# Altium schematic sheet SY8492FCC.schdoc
size 127 x 101 mm
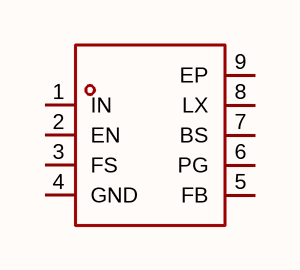
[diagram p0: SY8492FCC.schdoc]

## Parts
U?  sy8492fcc  [SO-8_L4.9-W3.9-P1.27-LS6.0-BL-EP]  (value not drawn)

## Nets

Not connected (* = marked no-connect by the designer): U? 1(IN) 2(EN) 3(FS) 4(GND) 5(FB) 6(PG) 7(BS) 8(LX) 9(EP)

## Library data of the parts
U? = sy8492fcc: 功能类型:降压型;工作电压:4.5V~60V;输出电压:800mV~60V;输出电流:2A;输出类型:可调;; Manufacturer: Silergy(矽力杰); AddInBom: yes; ModelId: 756fba4e187a48c69a2c935cd5c4465b; ModelName: SO-8_L4.9-W3.9-H1.5-LS5.9-P1.27; ModelTransform: 240.39054,192.913,0,270,0,0,0.004,-0.002,0; Function: 降压型; Output Current: 2A; Frequency - Switching: 100kHz~1MHz; Synchronous Rectifier: 否; Number of Outputs: 1; Topology: 降压式; Quiescent Current: 100uA; Switch tube (built-in/external): 内置; Output Type: 可调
